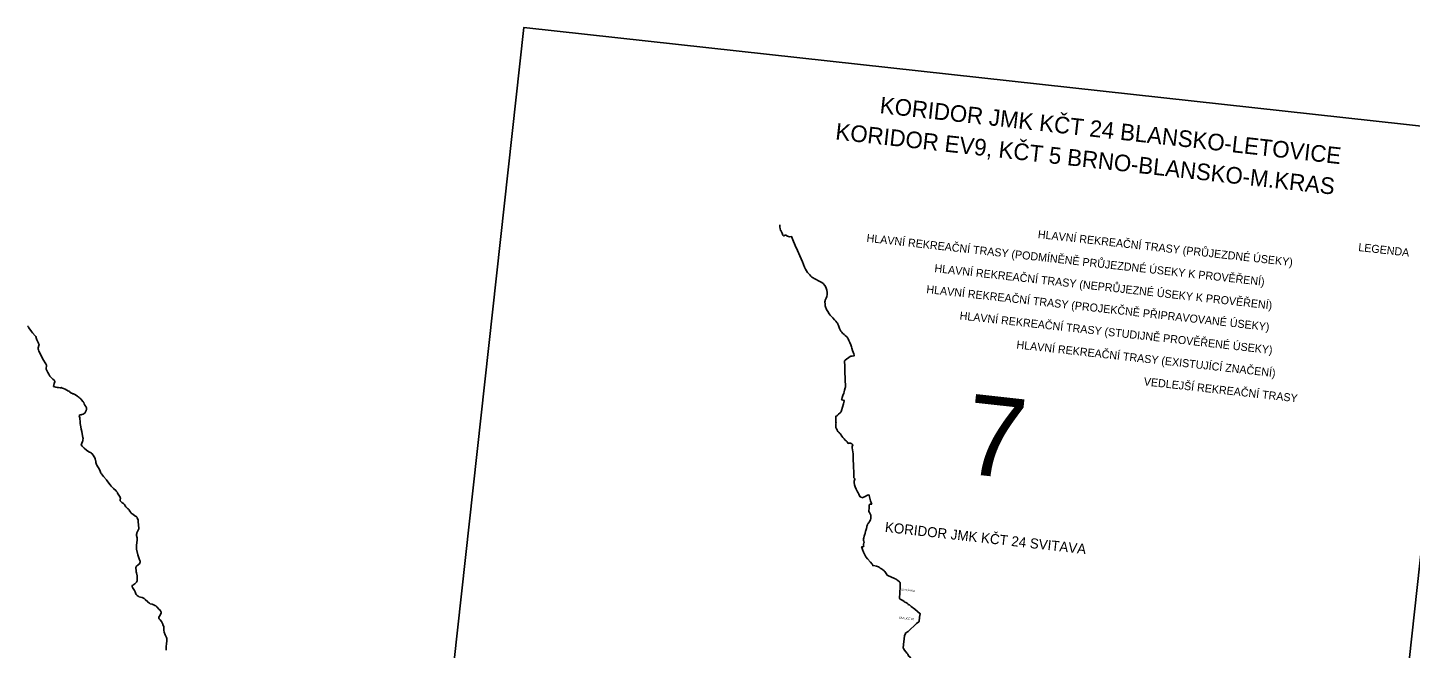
# Model space of a CAD drawing. Extents: x -678204 to -526855, y -1228851 to -1110393.
# Drawn here: x -620984 to -579529, y -1128993 to -1110393 of the extents above; entities that cross this region are included whole.
import ezdxf

# ---------------------------------------------------------------- set-up
doc = ezdxf.new("R2010")
doc.units = 0
for name, color, linetype in [('00_n_cyklo popisy', 7, 'Continuous'), ('00_n_cyklo popisy detaily', 7, 'Continuous'), ('00_n_cyklo prujezdne podminecne rekreacni hlavni', 7, 'Continuous'), ('00_n_cyklo prujezdne rekreacni hlavni', 7, 'Continuous'), ('00_n_cyklo trasovani rekreacni hlavni', 7, 'Continuous'), ('00_n_legenda popisy', 7, 'Continuous'), ('00_n_legenda popisy_hlavni', 7, 'Continuous'), ('_HELP BIG', 7, 'Continuous'), ('trasy_0001', 7, 'Continuous')]:
    doc.layers.add(name, color=color, linetype=linetype)

msp = doc.modelspace()

# ---------------------------------------------------------------- linework, layer by layer
at = {"layer": '00_n_cyklo prujezdne podminecne rekreacni hlavni'}
for points in [[(-594835, -1127514), (-594836, -1127513), (-594845, -1127494), (-594844, -1127447), (-594836, -1127368), (-594832, -1127293), (-594829, -1127193), (-594824, -1127112), (-594821, -1127052), (-594826, -1127024), (-594840, -1127004), (-594894, -1126959), (-594924, -1126936), (-594949, -1126922), (-594997, -1126901), (-595195, -1126814), (-595211, -1126804), (-595223, -1126777), (-595280, -1126690), (-595309, -1126667), (-595347, -1126640), (-595369, -1126623), (-595422, -1126587), (-595454, -1126565), (-595473, -1126555), (-595536, -1126532), (-595629, -1126514), (-595647, -1126512), (-595644, -1126492), (-595661, -1126469), (-595718, -1126408), (-595806, -1126308), (-595857, -1126253), (-595922, -1126107), (-595958, -1126027), (-595979, -1125973), (-595981, -1125950), (-595950, -1125948), (-595929, -1125942), (-595918, -1125940), (-595923, -1125902), (-595922, -1125871), (-595910, -1125830), (-595909, -1125825), (-595911, -1125786)], [(-594732, -1128992), (-594737, -1128984), (-594725, -1128874), (-594707, -1128710), (-594698, -1128618), (-594668, -1128553), (-594670, -1128543), (-594664, -1128529), (-594652, -1128529), (-594585, -1128486), (-594333, -1128248), (-594261, -1128196), (-594256, -1128187), (-594250, -1128054), (-594225, -1127957), (-594388, -1127824), (-594491, -1127736), (-594550, -1127692), (-594571, -1127685), (-594584, -1127665), (-594616, -1127638), (-594652, -1127618), (-594688, -1127608), (-594703, -1127591), (-594742, -1127561), (-594823, -1127518), (-594835, -1127514)], [(-594477, -1129352), (-594505, -1129307), (-594509, -1129295), (-594537, -1129252), (-594571, -1129220), (-594583, -1129195), (-594600, -1129171), (-594623, -1129137), (-594642, -1129109), (-594653, -1129098), (-594691, -1129050), (-594728, -1128999), (-594732, -1128992)]]:
    msp.add_lwpolyline(points, dxfattribs=at)
at = {"layer": '00_n_cyklo prujezdne rekreacni hlavni'}
for points in [[(-598085, -1116652), (-598144, -1116659), (-598198, -1116639), (-598256, -1116612), (-598275, -1116612), (-598289, -1116618), (-598302, -1116630), (-598309, -1116638), (-598333, -1116622), (-598345, -1116607), (-598351, -1116581), (-598361, -1116553), (-598383, -1116511), (-598404, -1116476), (-598413, -1116462), (-598425, -1116420), (-598428, -1116358), (-598428, -1116322), (-598435, -1116298)], [(-596305, -1119899), (-596308, -1119894), (-596335, -1119832), (-596362, -1119767), (-596384, -1119720), (-596397, -1119697), (-596426, -1119657), (-596472, -1119614), (-596505, -1119584), (-596549, -1119548), (-596578, -1119521), (-596599, -1119492), (-596614, -1119469), (-596642, -1119404), (-596676, -1119318), (-596691, -1119281), (-596708, -1119251), (-596728, -1119226), (-596757, -1119192), (-596794, -1119147), (-596844, -1119093), (-596885, -1119046), (-596921, -1119008), (-596949, -1118966), (-596998, -1118895), (-597034, -1118839), (-597047, -1118810), (-597055, -1118788), (-597069, -1118733), (-597074, -1118703), (-597075, -1118676), (-597079, -1118608), (-597076, -1118579), (-597070, -1118561), (-597045, -1118502), (-597023, -1118446), (-597012, -1118386), (-597011, -1118331), (-597019, -1118264), (-597029, -1118227), (-597056, -1118169), (-597087, -1118119), (-597134, -1118059), (-597174, -1118029), (-597251, -1117987), (-597470, -1117869), (-597505, -1117842), (-597537, -1117804), (-597577, -1117761), (-597606, -1117726), (-597636, -1117685), (-597663, -1117628), (-597695, -1117566), (-597757, -1117412), (-597834, -1117232), (-597903, -1117067), (-597968, -1116918), (-598038, -1116747), (-598082, -1116652), (-598085, -1116652)], [(-596249, -1122900), (-596247, -1122894), (-596276, -1122860), (-596311, -1122847), (-596330, -1122840), (-596356, -1122843), (-596382, -1122854), (-596400, -1122829), (-596415, -1122809), (-596447, -1122771), (-596469, -1122751), (-596504, -1122718), (-596543, -1122670), (-596575, -1122630), (-596591, -1122604), (-596614, -1122567), (-596630, -1122550), (-596662, -1122519), (-596672, -1122511), (-596689, -1122491), (-596709, -1122458), (-596718, -1122442), (-596734, -1122419), (-596750, -1122380), (-596749, -1122366), (-596752, -1122338), (-596752, -1122303), (-596751, -1122266), (-596748, -1122246), (-596752, -1122215), (-596753, -1122195), (-596755, -1122152), (-596756, -1122069), (-596757, -1122037), (-596737, -1122036), (-596726, -1122030), (-596718, -1122026), (-596705, -1122007), (-596677, -1121977), (-596627, -1121931), (-596604, -1121913), (-596593, -1121900), (-596581, -1121862), (-596556, -1121769), (-596527, -1121668), (-596500, -1121574), (-596503, -1121569), (-596574, -1121547), (-596580, -1121542), (-596577, -1121531), (-596563, -1121478), (-596546, -1121421), (-596518, -1121345), (-596501, -1121304), (-596489, -1121256), (-596469, -1121186), (-596467, -1121162), (-596467, -1121122), (-596467, -1121083), (-596472, -1120996), (-596473, -1120922), (-596473, -1120885), (-596477, -1120833), (-596479, -1120784), (-596481, -1120732), (-596479, -1120679), (-596479, -1120642), (-596482, -1120592), (-596484, -1120552), (-596491, -1120374), (-596474, -1120356), (-596320, -1120247), (-596300, -1120239), (-596269, -1120239), (-596207, -1120223), (-596198, -1120219), (-596202, -1120207), (-596213, -1120172), (-596232, -1120117), (-596250, -1120063), (-596270, -1119998), (-596285, -1119954), (-596295, -1119923), (-596304, -1119902), (-596305, -1119899)], [(-596212, -1123872), (-596216, -1123794), (-596217, -1123680), (-596220, -1123585), (-596224, -1123504), (-596230, -1123332), (-596233, -1123259), (-596235, -1123202), (-596236, -1123169), (-596246, -1123106), (-596256, -1123040), (-596265, -1122980), (-596267, -1122960), (-596264, -1122932), (-596249, -1122900)], [(-595979, -1124479), (-595998, -1124459), (-596011, -1124452), (-596025, -1124448), (-596043, -1124418), (-596062, -1124371), (-596083, -1124334), (-596105, -1124304), (-596146, -1124220), (-596178, -1124149), (-596190, -1124091), (-596200, -1124020), (-596207, -1123980), (-596180, -1123926), (-596182, -1123912), (-596203, -1123891), (-596212, -1123880), (-596212, -1123872)], [(-595979, -1124479), (-595892, -1124449), (-595804, -1124407), (-595762, -1124395), (-595757, -1124414), (-595718, -1124569), (-595687, -1124650), (-595679, -1124668), (-595678, -1124674), (-595683, -1124677), (-595691, -1124677), (-595727, -1124671), (-595736, -1124673), (-595744, -1124678), (-595751, -1124688), (-595757, -1124782), (-595762, -1124880), (-595756, -1124910), (-595745, -1124927), (-595730, -1124944), (-595721, -1124963), (-595709, -1125002), (-595701, -1125041), (-595704, -1125103), (-595717, -1125145), (-595744, -1125193), (-595764, -1125231), (-595774, -1125239), (-595790, -1125248), (-595798, -1125258), (-595803, -1125274), (-595808, -1125300), (-595811, -1125310), (-595821, -1125334), (-595823, -1125349), (-595834, -1125397)], [(-595911, -1125786), (-595912, -1125780), (-595922, -1125774), (-595922, -1125748), (-595921, -1125713), (-595916, -1125681), (-595904, -1125629), (-595897, -1125603), (-595883, -1125572), (-595877, -1125553), (-595862, -1125484), (-595856, -1125459), (-595834, -1125397)]]:
    msp.add_lwpolyline(points, dxfattribs=at)
at = {"layer": '00_n_cyklo trasovani rekreacni hlavni'}
for points in [[(-598085, -1116652), (-598144, -1116659), (-598198, -1116639), (-598256, -1116612), (-598275, -1116612), (-598289, -1116618), (-598302, -1116630), (-598309, -1116638), (-598333, -1116622), (-598345, -1116607), (-598351, -1116581), (-598361, -1116553), (-598383, -1116511), (-598404, -1116476), (-598413, -1116462), (-598425, -1116420), (-598428, -1116358), (-598428, -1116322), (-598435, -1116298)], [(-596305, -1119899), (-596308, -1119894), (-596335, -1119832), (-596362, -1119767), (-596384, -1119720), (-596397, -1119697), (-596426, -1119657), (-596472, -1119614), (-596505, -1119584), (-596549, -1119548), (-596578, -1119521), (-596599, -1119492), (-596614, -1119469), (-596642, -1119404), (-596676, -1119318), (-596691, -1119281), (-596708, -1119251), (-596728, -1119226), (-596757, -1119192), (-596794, -1119147), (-596844, -1119093), (-596885, -1119046), (-596921, -1119008), (-596949, -1118966), (-596998, -1118895), (-597034, -1118839), (-597047, -1118810), (-597055, -1118788), (-597069, -1118733), (-597074, -1118703), (-597075, -1118676), (-597079, -1118608), (-597076, -1118579), (-597070, -1118561), (-597045, -1118502), (-597023, -1118446), (-597012, -1118386), (-597011, -1118331), (-597019, -1118264), (-597029, -1118227), (-597056, -1118169), (-597087, -1118119), (-597134, -1118059), (-597174, -1118029), (-597251, -1117987), (-597470, -1117869), (-597505, -1117842), (-597537, -1117804), (-597577, -1117761), (-597606, -1117726), (-597636, -1117685), (-597663, -1117628), (-597695, -1117566), (-597757, -1117412), (-597834, -1117232), (-597903, -1117067), (-597968, -1116918), (-598038, -1116747), (-598082, -1116652), (-598085, -1116652)], [(-596249, -1122900), (-596247, -1122894), (-596276, -1122860), (-596311, -1122847), (-596330, -1122840), (-596356, -1122843), (-596382, -1122854), (-596400, -1122829), (-596415, -1122809), (-596447, -1122771), (-596469, -1122751), (-596504, -1122718), (-596543, -1122670), (-596575, -1122630), (-596591, -1122604), (-596614, -1122567), (-596630, -1122550), (-596662, -1122519), (-596672, -1122511), (-596689, -1122491), (-596709, -1122458), (-596718, -1122442), (-596734, -1122419), (-596750, -1122380), (-596749, -1122366), (-596752, -1122338), (-596752, -1122303), (-596751, -1122266), (-596748, -1122246), (-596752, -1122215), (-596753, -1122195), (-596755, -1122152), (-596756, -1122069), (-596757, -1122037), (-596737, -1122036), (-596726, -1122030), (-596718, -1122026), (-596705, -1122007), (-596677, -1121977), (-596627, -1121931), (-596604, -1121913), (-596593, -1121900), (-596581, -1121862), (-596556, -1121769), (-596527, -1121668), (-596500, -1121574), (-596503, -1121569), (-596574, -1121547), (-596580, -1121542), (-596577, -1121531), (-596563, -1121478), (-596546, -1121421), (-596518, -1121345), (-596501, -1121304), (-596489, -1121256), (-596469, -1121186), (-596467, -1121162), (-596467, -1121122), (-596467, -1121083), (-596472, -1120996), (-596473, -1120922), (-596473, -1120885), (-596477, -1120833), (-596479, -1120784), (-596481, -1120732), (-596479, -1120679), (-596479, -1120642), (-596482, -1120592), (-596484, -1120552), (-596491, -1120374), (-596474, -1120356), (-596320, -1120247), (-596300, -1120239), (-596269, -1120239), (-596207, -1120223), (-596198, -1120219), (-596202, -1120207), (-596213, -1120172), (-596232, -1120117), (-596250, -1120063), (-596270, -1119998), (-596285, -1119954), (-596295, -1119923), (-596304, -1119902), (-596305, -1119899)], [(-596212, -1123872), (-596216, -1123794), (-596217, -1123680), (-596220, -1123585), (-596224, -1123504), (-596230, -1123332), (-596233, -1123259), (-596235, -1123202), (-596236, -1123169), (-596246, -1123106), (-596256, -1123040), (-596265, -1122980), (-596267, -1122960), (-596264, -1122932), (-596249, -1122900)], [(-595979, -1124479), (-595998, -1124459), (-596011, -1124452), (-596025, -1124448), (-596043, -1124418), (-596062, -1124371), (-596083, -1124334), (-596105, -1124304), (-596146, -1124220), (-596178, -1124149), (-596190, -1124091), (-596200, -1124020), (-596207, -1123980), (-596180, -1123926), (-596182, -1123912), (-596203, -1123891), (-596212, -1123880), (-596212, -1123872)], [(-595979, -1124479), (-595892, -1124449), (-595804, -1124407), (-595762, -1124395), (-595757, -1124414), (-595718, -1124569), (-595687, -1124650), (-595679, -1124668), (-595678, -1124674), (-595683, -1124677), (-595691, -1124677), (-595727, -1124671), (-595736, -1124673), (-595744, -1124678), (-595751, -1124688), (-595757, -1124782), (-595762, -1124880), (-595756, -1124910), (-595745, -1124927), (-595730, -1124944), (-595721, -1124963), (-595709, -1125002), (-595701, -1125041), (-595704, -1125103), (-595717, -1125145), (-595744, -1125193), (-595764, -1125231), (-595774, -1125239), (-595790, -1125248), (-595798, -1125258), (-595803, -1125274), (-595808, -1125300), (-595811, -1125310), (-595821, -1125334), (-595823, -1125349), (-595834, -1125397)], [(-595911, -1125786), (-595912, -1125780), (-595922, -1125774), (-595922, -1125748), (-595921, -1125713), (-595916, -1125681), (-595904, -1125629), (-595897, -1125603), (-595883, -1125572), (-595877, -1125553), (-595862, -1125484), (-595856, -1125459), (-595834, -1125397)], [(-594835, -1127514), (-594836, -1127513), (-594845, -1127494), (-594844, -1127447), (-594836, -1127368), (-594832, -1127293), (-594829, -1127193), (-594824, -1127112), (-594821, -1127052), (-594826, -1127024), (-594840, -1127004), (-594894, -1126959), (-594924, -1126936), (-594949, -1126922), (-594997, -1126901), (-595195, -1126814), (-595211, -1126804), (-595223, -1126777), (-595280, -1126690), (-595309, -1126667), (-595347, -1126640), (-595369, -1126623), (-595422, -1126587), (-595454, -1126565), (-595473, -1126555), (-595536, -1126532), (-595629, -1126514), (-595647, -1126512), (-595644, -1126492), (-595661, -1126469), (-595718, -1126408), (-595806, -1126308), (-595857, -1126253), (-595922, -1126107), (-595958, -1126027), (-595979, -1125973), (-595981, -1125950), (-595950, -1125948), (-595929, -1125942), (-595918, -1125940), (-595923, -1125902), (-595922, -1125871), (-595910, -1125830), (-595909, -1125825), (-595911, -1125786)], [(-594732, -1128992), (-594737, -1128984), (-594725, -1128874), (-594707, -1128710), (-594698, -1128618), (-594668, -1128553), (-594670, -1128543), (-594664, -1128529), (-594652, -1128529), (-594585, -1128486), (-594333, -1128248), (-594261, -1128196), (-594256, -1128187), (-594250, -1128054), (-594225, -1127957), (-594388, -1127824), (-594491, -1127736), (-594550, -1127692), (-594571, -1127685), (-594584, -1127665), (-594616, -1127638), (-594652, -1127618), (-594688, -1127608), (-594703, -1127591), (-594742, -1127561), (-594823, -1127518), (-594835, -1127514)], [(-594477, -1129352), (-594505, -1129307), (-594509, -1129295), (-594537, -1129252), (-594571, -1129220), (-594583, -1129195), (-594600, -1129171), (-594623, -1129137), (-594642, -1129109), (-594653, -1129098), (-594691, -1129050), (-594728, -1128999), (-594732, -1128992)]]:
    msp.add_lwpolyline(points, dxfattribs=at)
at = {"layer": '_HELP BIG'}
msp.add_lwpolyline([(-580037, -1133644), (-608324, -1130538), (-606112, -1110393), (-577825, -1113499)], close=True, dxfattribs=at)
at = {"layer": 'trasy_0001'}
msp.add_lwpolyline([(-616830, -1129050), (-616830, -1128982), (-616830, -1128962), (-616820, -1128836), (-616814, -1128792), (-616809, -1128741), (-616809, -1128697), (-616819, -1128668), (-616846, -1128625), (-616853, -1128613), (-616863, -1128591), (-616888, -1128509), (-616900, -1128451), (-616900, -1128399), (-616904, -1128353), (-616927, -1128278), (-616933, -1128265), (-616940, -1128247), (-616950, -1128232), (-616976, -1128193), (-617015, -1128143), (-617029, -1128121), (-617038, -1128109), (-617051, -1128087), (-617051, -1128062), (-617034, -1128032), (-616982, -1127942), (-616977, -1127930), (-616980, -1127910), (-616990, -1127886), (-617000, -1127869), (-617022, -1127844), (-617037, -1127829), (-617114, -1127751), (-617145, -1127722), (-617170, -1127705), (-617186, -1127697), (-617208, -1127687), (-617250, -1127672), (-617309, -1127656), (-617335, -1127643), (-617361, -1127623), (-617376, -1127610), (-617382, -1127604), (-617456, -1127526), (-617491, -1127498), (-617529, -1127475), (-617551, -1127465), (-617603, -1127456), (-617638, -1127446), (-617652, -1127440), (-617665, -1127432), (-617675, -1127426), (-617701, -1127406), (-617716, -1127392), (-617729, -1127375), (-617738, -1127357), (-617762, -1127297), (-617779, -1127261), (-617837, -1127168), (-617844, -1127156), (-617849, -1127145), (-617851, -1127134), (-617851, -1127124), (-617838, -1127104), (-617835, -1127100), (-617803, -1127079), (-617769, -1127060), (-617759, -1127051), (-617722, -1127007), (-617710, -1126990), (-617703, -1126967), (-617698, -1126851), (-617699, -1126831), (-617700, -1126819), (-617723, -1126732), (-617728, -1126698), (-617733, -1126662), (-617738, -1126592), (-617736, -1126570), (-617732, -1126555), (-617716, -1126531), (-617670, -1126487), (-617634, -1126457), (-617616, -1126432), (-617610, -1126419), (-617610, -1126389), (-617613, -1126381), (-617627, -1126336), (-617676, -1126189), (-617719, -1126022), (-617721, -1126006), (-617716, -1125908), (-617703, -1125744), (-617698, -1125715), (-617699, -1125684), (-617718, -1125610), (-617720, -1125601), (-617720, -1125583), (-617715, -1125554), (-617707, -1125535), (-617689, -1125491), (-617651, -1125410), (-617649, -1125399), (-617666, -1125188), (-617669, -1125169), (-617675, -1125144), (-617697, -1125088), (-617701, -1125076), (-617707, -1125065), (-617713, -1125057), (-617723, -1125049), (-617734, -1125039), (-617767, -1125018), (-617828, -1124977), (-617852, -1124962), (-617876, -1124946), (-617883, -1124938), (-617893, -1124924), (-617919, -1124880), (-617926, -1124870), (-617943, -1124847), (-617955, -1124833), (-617973, -1124816), (-617992, -1124801), (-618013, -1124783), (-618036, -1124757), (-618057, -1124726), (-618081, -1124684), (-618099, -1124663), (-618110, -1124654), (-618126, -1124643), (-618159, -1124619), (-618193, -1124592), (-618200, -1124585), (-618208, -1124573), (-618211, -1124564), (-618211, -1124539), (-618206, -1124518), (-618204, -1124505), (-618203, -1124491), (-618208, -1124470), (-618212, -1124463), (-618253, -1124400), (-618289, -1124339), (-618293, -1124328), (-618306, -1124302), (-618316, -1124289), (-618331, -1124269), (-618407, -1124201), (-618479, -1124129), (-618510, -1124093), (-618607, -1123964), (-618623, -1123943), (-618712, -1123839), (-618773, -1123763), (-618786, -1123740), (-618808, -1123680), (-618829, -1123635), (-618906, -1123506), (-618918, -1123480), (-618926, -1123457), (-618936, -1123419), (-618941, -1123394), (-618951, -1123349), (-618956, -1123334), (-618957, -1123330), (-618959, -1123322), (-618960, -1123320), (-618962, -1123313), (-618974, -1123286), (-618988, -1123259), (-619021, -1123204), (-619060, -1123157), (-619081, -1123138), (-619101, -1123127), (-619128, -1123113), (-619151, -1123100), (-619216, -1123052), (-619289, -1122992), (-619351, -1122938), (-619384, -1122899), (-619341, -1122795), (-619333, -1122773), (-619328, -1122744), (-619324, -1122700), (-619327, -1122677), (-619339, -1122624), (-619364, -1122492), (-619376, -1122427), (-619390, -1122360), (-619399, -1122307), (-619406, -1122252), (-619408, -1122232), (-619412, -1122193), (-619413, -1122182), (-619417, -1122126), (-619424, -1122085), (-619435, -1122022), (-619432, -1122009), (-619423, -1121999), (-619411, -1121994), (-619404, -1121992), (-619380, -1121993), (-619360, -1121987), (-619321, -1121971), (-619287, -1121954), (-619272, -1121944), (-619261, -1121929), (-619249, -1121910), (-619235, -1121886), (-619232, -1121878), (-619228, -1121864), (-619226, -1121859), (-619221, -1121844), (-619216, -1121807), (-619218, -1121780), (-619225, -1121762), (-619237, -1121741), (-619265, -1121704), (-619285, -1121662), (-619304, -1121627), (-619323, -1121602), (-619381, -1121533), (-619391, -1121521), (-619416, -1121497), (-619435, -1121480), (-619469, -1121452), (-619481, -1121443), (-619491, -1121435), (-619569, -1121386), (-619583, -1121379), (-619594, -1121375), (-619611, -1121370), (-619632, -1121362), (-619661, -1121349), (-619674, -1121343), (-619720, -1121313), (-619734, -1121301), (-619752, -1121290), (-619777, -1121273), (-619788, -1121268), (-619814, -1121255), (-619864, -1121228), (-619885, -1121217), (-619901, -1121211), (-619938, -1121195), (-619967, -1121188), (-619967, -1121182), (-619969, -1121178), (-619975, -1121175), (-619984, -1121178), (-619987, -1121186), (-620014, -1121182), (-620059, -1121179), (-620078, -1121175), (-620101, -1121172), (-620138, -1121163), (-620209, -1121143), (-620186, -1121053), (-620171, -1121002), (-620173, -1120989), (-620180, -1120982), (-620179, -1120970), (-620188, -1120957), (-620229, -1120923), (-620264, -1120892), (-620317, -1120841), (-620353, -1120779), (-620382, -1120722), (-620420, -1120650), (-620430, -1120625), (-620430, -1120606), (-620428, -1120591), (-620422, -1120549), (-620421, -1120516), (-620424, -1120508), (-620430, -1120492), (-620435, -1120482), (-620442, -1120471), (-620460, -1120442), (-620511, -1120353), (-620645, -1120092), (-620661, -1120048), (-620667, -1120028), (-620670, -1120011), (-620667, -1119987), (-620644, -1119921), (-620642, -1119904), (-620643, -1119891), (-620646, -1119877), (-620657, -1119854), (-620659, -1119848), (-620679, -1119808), (-620707, -1119745), (-620728, -1119689), (-620732, -1119681), (-620743, -1119653), (-620755, -1119633), (-620836, -1119534), (-620866, -1119499), (-620922, -1119432), (-620927, -1119422), (-620944, -1119393), (-620957, -1119370), (-620965, -1119358), (-620971, -1119351), (-620984, -1119341)], dxfattribs=at)

# ---------------------------------------------------------------- texts
at = {"layer": '00_n_cyklo popisy'}
msp.add_text('KORIDOR JMK KČT 24 SVITAVA', height=300, rotation=353.6836, dxfattribs=at).set_placement((-595293, -1125504))
at = {"layer": '00_n_cyklo popisy detaily'}
for s, p in [('SVITÁVKA', (-594793, -1127260)), ('SKALICE 02', (-594869, -1128099))]:
    msp.add_text(s, height=60, rotation=353.6836, dxfattribs=at).set_placement(p)
at = {"layer": '00_n_legenda popisy'}
for s, p in [('HLAVNÍ REKREAČNÍ TRASY (PODMÍNĚNĚ PRŮJEZDNÉ ÚSEKY K PROVĚŘENÍ) ', (-595841, -1116810)), ('HLAVNÍ REKREAČNÍ TRASY (PRŮJEZDNÉ ÚSEKY) ', (-590706, -1116697)), ('LEGENDA', (-581099, -1117085)), ('HLAVNÍ REKREAČNÍ TRASY (NEPRŮJEZNÉ ÚSEKY K PROVĚŘENÍ) ', (-593806, -1117716)), ('HLAVNÍ REKREAČNÍ TRASY (PROJEKČNĚ PŘIPRAVOVANÉ ÚSEKY) ', (-594048, -1118345)), ('HLAVNÍ REKREAČNÍ TRASY (STUDIJNĚ PROVĚŘENÉ ÚSEKY) ', (-593051, -1119136)), ('HLAVNÍ REKREAČNÍ TRASY (EXISTUJÍCÍ ZNAČENÍ) ', (-591347, -1120006)), ('VEDLEJŠÍ REKREAČNÍ TRASY ', (-587530, -1121110))]:
    msp.add_text(s, height=240, rotation=353.6836, dxfattribs=at).set_placement(p)
at = {"layer": '00_n_legenda popisy_hlavni'}
for s, p in [('KORIDOR JMK KČT 24 BLANSKO-LETOVICE', (-595453, -1112954)), ('KORIDOR EV9, KČT 5 BRNO-BLANSKO-M.KRAS', (-596783, -1113743))]:
    msp.add_text(s, height=497.66, rotation=353.6836, dxfattribs=at).set_placement(p)
at = {"layer": '_HELP BIG'}
msp.add_text('7', height=2400, rotation=353.6836, dxfattribs=at).set_placement((-592977, -1123741))

doc.saveas('drawing.dxf')
